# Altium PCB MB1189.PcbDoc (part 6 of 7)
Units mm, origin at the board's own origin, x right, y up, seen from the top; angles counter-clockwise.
Board outline 60.03 x 127.03 mm, 6 copper layers (TOP, L2_GND, L3_VCC, L4_SIG, L5_GND, BOTTOM), stack 1.58 mm thick; 273 components, 264 nets, 1114 pads, 811 vias.
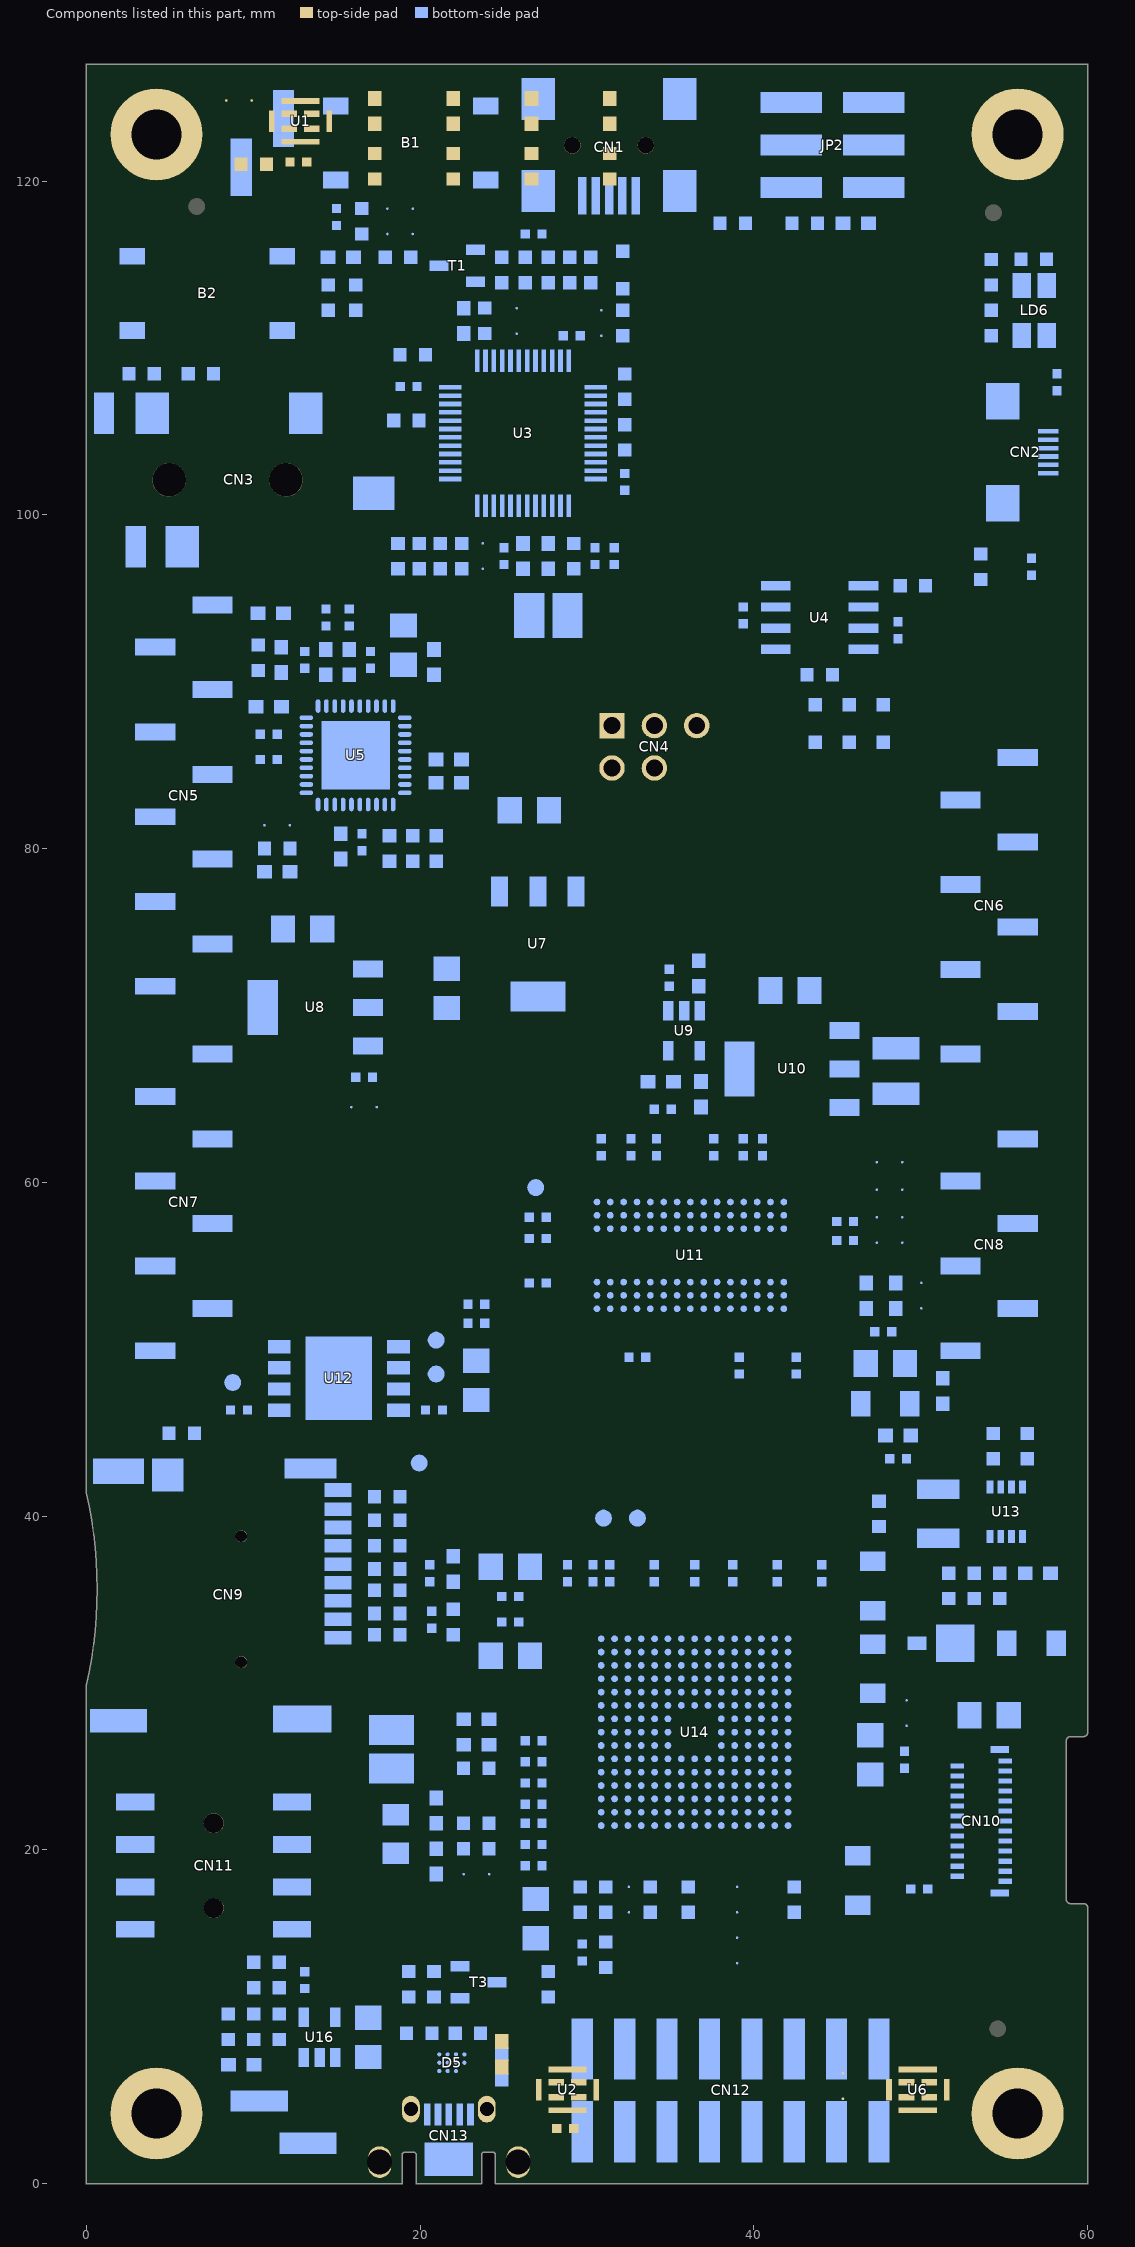
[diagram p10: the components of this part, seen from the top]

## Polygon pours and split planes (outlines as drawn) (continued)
GND on L4_SIG "L4_SIG_GND_P038" (solid, remove dead copper, pour order 38): 21.057,26.848 25.73,26.848 26.492,26.086 26.492,20.498 27.076,19.914 27.076,16.739 26.772,16.434 26.721,16.383 23.495,16.383 16.51,16.383 14.757,18.136 14.757,34.315 13.767,35.306 13.767,39.167 11.989,40.945 9.957,40.945 6.629,44.272 6.629,52.984 5.029,54.585 5.029,58.801 4.42,59.411 4.42,65.634 4.991,66.205 4.991,78.359 9.144,82.512 9.22,82.917 9.22,86.843 8.128,87.935 8.128,92.837 9.22,93.929 13.31,93.929 13.513,93.726 13.513,92.507 13.31,92.304 12.243,92.304 10.058,92.304 9.474,91.719 9.474,91.059 11.481,89.052 11.481,81.915 7.061,77.495 7.061,65.761 5.588,64.287 5.588,60.198 6.909,58.877 6.909,54.839 8.331,53.416 8.331,45.263 10.922,42.672 12.573,42.672 14.859,40.386 14.859,35.941 15.875,34.925 15.875,32.029 21.057,26.848
GND on L4_SIG "L4_SIG_GND_P036" (solid, remove dead copper, pour order 36): 23.724,96.672 31.471,96.672 32.131,96.012 32.131,90.297 31.877,90.043 23.495,90.043 23.114,90.424 23.114,96.063 23.724,96.672
GND on L2_GND (split plane): 211 vertices, not listed, extent 0.5,0.5 59.5,126.5
+3V3 on L3_VCC (split plane): 202 vertices, not listed, extent 0.501,0.501 59.499,126.499
VDD_MCU on L3_VCC (split plane): 25.73,54.291 26.403,53.618 26.414,53.593 26.414,43.815 26.423,43.749 26.432,43.725 26.434,43.717 26.438,43.71 26.448,43.687 26.489,43.634 26.997,43.126 27.05,43.085 27.073,43.075 27.08,43.071 27.088,43.069 27.112,43.06 27.178,43.051 46.353,43.051 46.353,39.603 44.523,37.773 44.482,37.72 44.472,37.697 44.468,37.69 44.466,37.682 44.457,37.658 44.448,37.592 44.448,22.204 42.947,20.703 30.988,20.703 30.922,20.694 30.898,20.685 30.89,20.683 30.883,20.679 30.878,20.676 30.86,20.669 30.807,20.628 27.961,17.782 18.796,17.782 18.73,17.773 18.706,17.764 18.698,17.762 18.691,17.758 18.668,17.748 18.615,17.707 14.043,13.135 14.002,13.082 13.992,13.059 13.988,13.052 13.986,13.044 13.977,13.02 13.968,12.954 13.968,8.763 13.968,4.932 13.483,4.447 9.631,4.447 9.273,4.805 9.273,16.785 12.881,20.393 12.922,20.446 12.929,20.464 12.932,20.469 12.936,20.476 12.938,20.484 12.947,20.508 12.956,20.574 12.956,28.85 14.457,30.351 17.653,30.351 17.719,30.36 17.743,30.369 17.751,30.371 17.758,30.375 17.781,30.385 17.834,30.426 18.85,31.442 18.891,31.495 18.901,31.518 18.905,31.525 18.907,31.533 18.909,31.539 18.916,31.557 18.925,31.623 18.925,53.72 18.936,53.745 19.482,54.291 19.531,54.311 25.681,54.311
+5V on L3_VCC (split plane): 223 vertices, not listed, extent 14.48,9.019 55.751,119.632
+3V3_ST_LINK on L3_VCC (split plane): 30.351,116.713 30.36,116.647 30.369,116.623 30.371,116.615 30.375,116.608 30.385,116.585 30.426,116.532 31.315,115.643 31.368,115.602 31.391,115.592 31.398,115.588 31.406,115.586 31.43,115.577 31.496,115.568 33.493,115.568 33.489,115.536 33.489,97.536 33.495,97.484 25.6,89.589 25.559,89.536 25.549,89.513 25.545,89.506 25.543,89.498 25.534,89.474 25.525,89.408 25.525,82.169 25.534,82.103 25.543,82.079 25.545,82.071 25.549,82.064 25.559,82.041 25.6,81.988 26.489,81.099 26.542,81.058 26.565,81.048 26.572,81.044 26.58,81.042 26.604,81.033 26.67,81.024 32.004,81.024 32.07,81.033 32.094,81.042 32.102,81.044 32.109,81.048 32.132,81.058 32.185,81.099 32.693,81.607 32.734,81.66 32.744,81.683 32.748,81.69 32.75,81.698 32.759,81.722 32.768,81.788 32.768,85.492 33.253,85.977 38.756,85.977 41.273,83.46 41.273,62.359 22.204,62.359 18.925,65.638 18.925,101.854 18.916,101.92 18.907,101.944 18.905,101.952 18.901,101.959 18.891,101.982 18.85,102.035 16.893,103.992 16.893,110.511 26.014,119.632 30.351,119.632
GND on L5_GND (split plane): 208 vertices, not listed, extent 0.5,0.5 59.5,126.5

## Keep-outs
TOP:
  region: 13.073,60.157 13.073,58.417 13.2,58.29 25.525,58.29 25.655,58.42 25.655,60.155 25.528,60.282 13.198,60.282
  region: 13.073,60.407 13.073,62.23 23.75,62.23 23.875,62.105 23.875,60.53 23.627,60.282 13.198,60.282
  region: 8.263,118.491 8.231,118.815 8.137,119.126 7.983,119.413 7.777,119.664 7.526,119.87 7.239,120.024 6.928,120.118 6.604,120.15 6.28,120.118 5.969,120.024 5.778,119.922 5.682,119.87 5.431,119.664 5.225,119.413 5.071,119.126 4.977,118.815 4.945,118.491 4.977,118.167 5.071,117.856 5.225,117.569 5.431,117.318 5.682,117.112 5.778,117.06 5.969,116.958 6.28,116.864 6.604,116.832 6.928,116.864 7.239,116.958 7.526,117.112 7.777,117.318 7.983,117.569 8.137,117.856 8.231,118.167 8.263,118.491
  region: 56.269,9.271 56.237,9.595 56.143,9.906 55.989,10.193 55.783,10.444 55.532,10.65 55.245,10.804 54.934,10.898 54.61,10.93 54.286,10.898 53.975,10.804 53.784,10.702 53.688,10.65 53.437,10.444 53.231,10.193 53.077,9.906 52.983,9.595 52.951,9.271 52.983,8.947 53.077,8.636 53.231,8.349 53.437,8.098 53.688,7.892 53.784,7.84 53.975,7.738 54.286,7.644 54.61,7.612 54.934,7.644 55.245,7.738 55.532,7.892 55.783,8.098 55.989,8.349 56.143,8.636 56.237,8.947 56.269,9.271
  region: 56.015,118.11 55.983,118.434 55.889,118.745 55.735,119.032 55.529,119.283 55.278,119.489 54.991,119.643 54.68,119.737 54.356,119.769 54.032,119.737 53.721,119.643 53.53,119.541 53.434,119.489 53.183,119.283 52.977,119.032 52.823,118.745 52.729,118.434 52.697,118.11 52.729,117.786 52.823,117.475 52.977,117.188 53.183,116.937 53.434,116.731 53.53,116.679 53.721,116.577 54.032,116.483 54.356,116.451 54.68,116.483 54.991,116.577 55.278,116.731 55.529,116.937 55.735,117.188 55.889,117.475 55.983,117.786 56.015,118.11
BOTTOM:
  region: 8.135,118.491 8.106,118.79 8.019,119.077 7.877,119.342 7.687,119.574 7.455,119.764 7.19,119.906 6.903,119.993 6.604,120.022 6.305,119.993 6.018,119.906 5.842,119.812 5.753,119.764 5.521,119.574 5.331,119.342 5.189,119.077 5.102,118.79 5.073,118.491 5.102,118.192 5.189,117.905 5.331,117.64 5.521,117.408 5.753,117.218 5.842,117.17 6.018,117.076 6.305,116.989 6.604,116.96 6.903,116.989 7.19,117.076 7.455,117.218 7.687,117.408 7.877,117.64 8.019,117.905 8.106,118.192 8.135,118.491
  region: 8.263,118.491 8.231,118.815 8.137,119.126 7.983,119.413 7.777,119.664 7.526,119.87 7.239,120.024 6.928,120.118 6.604,120.15 6.28,120.118 5.969,120.024 5.778,119.922 5.682,119.87 5.431,119.664 5.225,119.413 5.071,119.126 4.977,118.815 4.945,118.491 4.977,118.167 5.071,117.856 5.225,117.569 5.431,117.318 5.682,117.112 5.778,117.06 5.969,116.958 6.28,116.864 6.604,116.832 6.928,116.864 7.239,116.958 7.526,117.112 7.777,117.318 7.983,117.569 8.137,117.856 8.231,118.167 8.263,118.491
  region: 56.015,118.11 55.983,118.434 55.889,118.745 55.735,119.032 55.529,119.283 55.278,119.489 54.991,119.643 54.68,119.737 54.356,119.769 54.032,119.737 53.721,119.643 53.53,119.541 53.434,119.489 53.183,119.283 52.977,119.032 52.823,118.745 52.729,118.434 52.697,118.11 52.729,117.786 52.823,117.475 52.977,117.188 53.183,116.937 53.434,116.731 53.53,116.679 53.721,116.577 54.032,116.483 54.356,116.451 54.68,116.483 54.991,116.577 55.278,116.731 55.529,116.937 55.735,117.188 55.889,117.475 55.983,117.786 56.015,118.11
  region: 55.887,118.11 55.858,118.409 55.771,118.696 55.629,118.961 55.439,119.193 55.207,119.383 54.942,119.525 54.655,119.612 54.356,119.641 54.057,119.612 53.77,119.525 53.594,119.431 53.505,119.383 53.273,119.193 53.083,118.961 52.941,118.696 52.854,118.409 52.825,118.11 52.854,117.811 52.941,117.524 53.083,117.259 53.273,117.027 53.505,116.837 53.594,116.789 53.77,116.695 54.057,116.608 54.356,116.579 54.655,116.608 54.942,116.695 55.207,116.837 55.439,117.027 55.629,117.259 55.771,117.524 55.858,117.811 55.887,118.11
  region: 56.269,9.271 56.237,9.595 56.143,9.906 55.989,10.193 55.783,10.444 55.532,10.65 55.245,10.804 54.934,10.898 54.61,10.93 54.286,10.898 53.975,10.804 53.784,10.702 53.688,10.65 53.437,10.444 53.231,10.193 53.077,9.906 52.983,9.595 52.951,9.271 52.983,8.947 53.077,8.636 53.231,8.349 53.437,8.098 53.688,7.892 53.784,7.84 53.975,7.738 54.286,7.644 54.61,7.612 54.934,7.644 55.245,7.738 55.532,7.892 55.783,8.098 55.989,8.349 56.143,8.636 56.237,8.947 56.269,9.271
  region: 56.141,9.271 56.112,9.57 56.025,9.857 55.883,10.122 55.693,10.354 55.461,10.544 55.196,10.686 54.909,10.773 54.61,10.802 54.311,10.773 54.024,10.686 53.848,10.592 53.759,10.544 53.527,10.354 53.337,10.122 53.195,9.857 53.108,9.57 53.079,9.271 53.108,8.972 53.195,8.685 53.337,8.42 53.527,8.188 53.759,7.998 53.848,7.95 54.024,7.856 54.311,7.769 54.61,7.74 54.909,7.769 55.196,7.856 55.461,7.998 55.693,8.188 55.883,8.42 56.025,8.685 56.112,8.972 56.141,9.271
  region: 56.015,118.11 55.983,118.434 55.889,118.745 55.735,119.032 55.529,119.283 55.278,119.489 54.991,119.643 54.68,119.737 54.356,119.769 54.032,119.737 53.721,119.643 53.53,119.541 53.434,119.489 53.183,119.283 52.977,119.032 52.823,118.745 52.729,118.434 52.697,118.11 52.729,117.786 52.823,117.475 52.977,117.188 53.183,116.937 53.434,116.731 53.53,116.679 53.721,116.577 54.032,116.483 54.356,116.451 54.68,116.483 54.991,116.577 55.278,116.731 55.529,116.937 55.735,117.188 55.889,117.475 55.983,117.786 56.015,118.11
  region: 8.263,118.491 8.231,118.815 8.137,119.126 7.983,119.413 7.777,119.664 7.526,119.87 7.239,120.024 6.928,120.118 6.604,120.15 6.28,120.118 5.969,120.024 5.778,119.922 5.682,119.87 5.431,119.664 5.225,119.413 5.071,119.126 4.977,118.815 4.945,118.491 4.977,118.167 5.071,117.856 5.225,117.569 5.431,117.318 5.682,117.112 5.778,117.06 5.969,116.958 6.28,116.864 6.604,116.832 6.928,116.864 7.239,116.958 7.526,117.112 7.777,117.318 7.983,117.569 8.137,117.856 8.231,118.167 8.263,118.491
  region: 8.135,118.491 8.106,118.79 8.019,119.077 7.877,119.342 7.687,119.574 7.455,119.764 7.19,119.906 6.903,119.993 6.604,120.022 6.305,119.993 6.018,119.906 5.842,119.812 5.753,119.764 5.521,119.574 5.331,119.342 5.189,119.077 5.102,118.79 5.073,118.491 5.102,118.192 5.189,117.905 5.331,117.64 5.521,117.408 5.753,117.218 5.842,117.17 6.018,117.076 6.305,116.989 6.604,116.96 6.903,116.989 7.19,117.076 7.455,117.218 7.687,117.408 7.877,117.64 8.019,117.905 8.106,118.192 8.135,118.491
  region: 55.887,118.11 55.858,118.409 55.771,118.696 55.629,118.961 55.439,119.193 55.207,119.383 54.942,119.525 54.655,119.612 54.356,119.641 54.057,119.612 53.77,119.525 53.594,119.431 53.505,119.383 53.273,119.193 53.083,118.961 52.941,118.696 52.854,118.409 52.825,118.11 52.854,117.811 52.941,117.524 53.083,117.259 53.273,117.027 53.505,116.837 53.594,116.789 53.77,116.695 54.057,116.608 54.356,116.579 54.655,116.608 54.942,116.695 55.207,116.837 55.439,117.027 55.629,117.259 55.771,117.524 55.858,117.811 55.887,118.11
  region: 56.269,9.271 56.237,9.595 56.143,9.906 55.989,10.193 55.783,10.444 55.532,10.65 55.245,10.804 54.934,10.898 54.61,10.93 54.286,10.898 53.975,10.804 53.784,10.702 53.688,10.65 53.437,10.444 53.231,10.193 53.077,9.906 52.983,9.595 52.951,9.271 52.983,8.947 53.077,8.636 53.231,8.349 53.437,8.098 53.688,7.892 53.784,7.84 53.975,7.738 54.286,7.644 54.61,7.612 54.934,7.644 55.245,7.738 55.532,7.892 55.783,8.098 55.989,8.349 56.143,8.636 56.237,8.947 56.269,9.271
  region: 56.141,9.271 56.112,9.57 56.025,9.857 55.883,10.122 55.693,10.354 55.461,10.544 55.196,10.686 54.909,10.773 54.61,10.802 54.311,10.773 54.024,10.686 53.848,10.592 53.759,10.544 53.527,10.354 53.337,10.122 53.195,9.857 53.108,9.57 53.079,9.271 53.108,8.972 53.195,8.685 53.337,8.42 53.527,8.188 53.759,7.998 53.848,7.95 54.024,7.856 54.311,7.769 54.61,7.74 54.909,7.769 55.196,7.856 55.461,7.998 55.693,8.188 55.883,8.42 56.025,8.685 56.112,8.972 56.141,9.271
Multi-Layer:
  region: 33.492,97.028 52.508,97.028 52.508,116.044 33.492,116.044

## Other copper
TOP:
  pour cut-out: 17.231,96.774 17.195,96.953 17.094,97.104 16.943,97.205 16.764,97.241 16.585,97.205 16.535,97.171 16.434,97.104 16.333,96.953 16.297,96.774 16.333,96.595 16.434,96.444 16.535,96.377 16.585,96.343 16.764,96.307 16.943,96.343 17.094,96.444 17.195,96.595 17.231,96.774
  pour cut-out: 18.196,90.932 18.16,91.111 18.059,91.262 17.908,91.363 17.729,91.399 17.551,91.363 17.5,91.329 17.399,91.262 17.298,91.111 17.263,90.932 17.298,90.753 17.399,90.602 17.5,90.535 17.551,90.501 17.729,90.465 17.908,90.501 18.059,90.602 18.16,90.753 18.196,90.932
  pour cut-out: 17.846,81.808 17.81,81.987 17.709,82.138 17.558,82.239 17.379,82.275 17.2,82.239 17.15,82.205 17.049,82.138 16.948,81.987 16.912,81.808 16.948,81.629 17.049,81.478 17.15,81.411 17.2,81.377 17.379,81.341 17.558,81.377 17.709,81.478 17.81,81.629 17.846,81.808
  pour cut-out: 13.294,89.916 13.258,90.095 13.157,90.246 13.006,90.347 12.827,90.383 12.648,90.347 12.598,90.313 12.497,90.246 12.396,90.095 12.36,89.916 12.396,89.737 12.497,89.586 12.598,89.519 12.648,89.485 12.827,89.449 13.006,89.485 13.157,89.586 13.258,89.737 13.294,89.916
  pour cut-out: 12.129,93.472 12.15,93.443 12.168,93.413 12.184,93.381 12.197,93.348 12.206,93.314 12.213,93.279 12.217,93.244 12.218,93.208 12.215,93.173 12.21,93.138 12.201,93.103 12.19,93.07 12.176,93.037 12.158,93.006 12.139,92.977 12.116,92.949 12.092,92.923 12.065,92.9 12.036,92.879 12.006,92.861 11.974,92.845 11.941,92.832 11.907,92.823 11.872,92.816 11.837,92.812 11.801,92.811 11.766,92.814 11.731,92.819 11.696,92.828 11.663,92.839 11.63,92.853 11.599,92.871 11.57,92.89 11.542,92.913 11.516,92.937 11.493,92.964 11.472,92.993 11.454,93.023 11.438,93.055 11.425,93.088 11.416,93.122 11.409,93.157 11.405,93.192 11.404,93.228 11.407,93.263 11.412,93.298 11.421,93.333 11.432,93.366 11.446,93.399 11.464,93.43 11.483,93.459 11.493,93.472 11.493,93.959 17.335,99.801 17.335,102.544 19.748,104.957 19.748,107.447 20.256,107.955 20.256,111.815 20.88,112.44 20.883,112.456 20.89,112.491 20.9,112.525 20.912,112.558 20.928,112.59 20.946,112.62 20.967,112.649 20.991,112.676 21.016,112.7 21.044,112.723 21.074,112.743 21.105,112.76 21.137,112.774 21.171,112.785 21.205,112.794 21.24,112.799 21.276,112.802 21.311,112.801 21.346,112.797 21.381,112.79 21.415,112.781 21.448,112.768 21.48,112.752 21.511,112.734 21.539,112.713 21.566,112.689 21.591,112.664 21.613,112.636 21.633,112.607 21.65,112.576 21.664,112.543 21.676,112.51 21.684,112.475 21.69,112.44 21.692,112.405 21.691,112.369 21.687,112.334 21.681,112.299 21.671,112.265 21.658,112.232 21.642,112.2 21.624,112.17 21.603,112.141 21.58,112.114 21.554,112.09 21.526,112.067 21.497,112.047 21.466,112.03 21.433,112.016 21.4,112.005 21.365,111.996 21.346,111.993 21.33,111.99 20.892,111.552 20.892,107.691 20.384,107.183 20.384,104.694 17.971,102.281 17.971,99.538 12.129,93.696 12.129,93.472
  pour cut-out: 24.385,23.533 24.385,17.615 24.411,17.592 24.436,17.566 24.458,17.538 24.478,17.509 24.495,17.478 24.509,17.445 24.521,17.411 24.529,17.377 24.534,17.342 24.537,17.307 24.536,17.271 24.532,17.236 24.525,17.201 24.515,17.167 24.503,17.134 24.487,17.102 24.468,17.072 24.447,17.043 24.424,17.016 24.398,16.992 24.371,16.969 24.341,16.95 24.31,16.933 24.278,16.918 24.244,16.907 24.21,16.898 24.175,16.893 24.139,16.891 24.104,16.891 24.068,16.895 24.034,16.902 23.999,16.912 23.966,16.925 23.934,16.941 23.904,16.959 23.875,16.98 23.849,17.003 23.824,17.029 23.802,17.057 23.782,17.086 23.765,17.117 23.751,17.15 23.739,17.183 23.731,17.218 23.726,17.253 23.723,17.288 23.724,17.324 23.728,17.359 23.735,17.394 23.745,17.428 23.757,17.461 23.773,17.493 23.792,17.523 23.813,17.552 23.836,17.579 23.862,17.603 23.875,17.615 23.875,23.533 23.849,23.556 23.824,23.582 23.802,23.61 23.782,23.639 23.765,23.67 23.751,23.703 23.739,23.737 23.731,23.771 23.726,23.806 23.723,23.841 23.724,23.877 23.728,23.912 23.735,23.947 23.745,23.981 23.757,24.014 23.773,24.046 23.792,24.076 23.813,24.105 23.836,24.132 23.862,24.156 23.889,24.179 23.919,24.198 23.95,24.215 23.982,24.23 24.016,24.241 24.05,24.25 24.085,24.255 24.121,24.257 24.156,24.257 24.192,24.253 24.226,24.246 24.261,24.236 24.294,24.223 24.326,24.207 24.356,24.189 24.385,24.168 24.411,24.145 24.436,24.119 24.458,24.091 24.478,24.062 24.495,24.031 24.509,23.998 24.521,23.965 24.529,23.93 24.534,23.895 24.537,23.86 24.536,23.824 24.532,23.789 24.525,23.754 24.515,23.72 24.503,23.687 24.487,23.655 24.468,23.625 24.447,23.596 24.424,23.569 24.398,23.545 24.385,23.533
  pour cut-out: 23.021,17.272 22.989,17.431 22.899,17.565 22.765,17.655 22.606,17.687 22.447,17.655 22.402,17.625 22.313,17.565 22.223,17.431 22.191,17.272 22.223,17.113 22.313,16.979 22.402,16.919 22.447,16.889 22.606,16.857 22.765,16.889 22.899,16.979 22.989,17.113 23.021,17.272
  text "1" at 13.805,60.82 h1.4
  text "B" at 13.729,58.801 h1.4
  text "TOP" at 55.499,-49.276 h1.52
  text "1" at 62.24,-49.31 h1.91
  text ".GTL" at 97.47,-49.4 h1.52
L4_SIG:
  pour cut-out: 24.545,23.851 24.513,24.009 24.423,24.144 24.289,24.234 24.13,24.265 23.971,24.234 23.926,24.204 23.837,24.144 23.747,24.009 23.715,23.851 23.747,23.692 23.837,23.557 23.926,23.497 23.971,23.467 24.13,23.436 24.289,23.467 24.423,23.557 24.513,23.692 24.545,23.851
  pour cut-out: 18.628,78.232 18.592,78.411 18.491,78.562 18.34,78.663 18.161,78.699 17.982,78.663 17.932,78.629 17.831,78.562 17.73,78.411 17.694,78.232 17.73,78.053 17.831,77.902 17.932,77.835 17.982,77.801 18.161,77.765 18.34,77.801 18.491,77.902 18.592,78.053 18.628,78.232
  pour cut-out: 20.025,78.232 19.989,78.411 19.888,78.562 19.737,78.663 19.558,78.699 19.379,78.663 19.329,78.629 19.228,78.562 19.127,78.411 19.091,78.232 19.127,78.053 19.228,77.902 19.329,77.835 19.379,77.801 19.558,77.765 19.737,77.801 19.888,77.902 19.989,78.053 20.025,78.232
  pour cut-out: 17.436,89.388 17.4,89.567 17.299,89.718 17.148,89.819 16.969,89.855 16.79,89.819 16.74,89.785 16.639,89.718 16.538,89.567 16.502,89.388 16.538,89.21 16.639,89.058 16.74,88.991 16.79,88.957 16.969,88.922 17.148,88.957 17.299,89.058 17.4,89.21 17.436,89.388
  pour cut-out: 16.977,78.842 16.941,79.02 16.84,79.172 16.689,79.273 16.51,79.308 16.331,79.273 16.281,79.239 16.18,79.172 16.079,79.02 16.043,78.842 16.079,78.663 16.18,78.512 16.281,78.444 16.331,78.41 16.51,78.375 16.689,78.41 16.84,78.512 16.941,78.663 16.977,78.842
  pour cut-out: 14.945,78.613 14.909,78.792 14.808,78.943 14.657,79.044 14.478,79.08 14.299,79.044 14.249,79.01 14.148,78.943 14.047,78.792 14.011,78.613 14.047,78.434 14.148,78.283 14.249,78.216 14.299,78.182 14.478,78.146 14.657,78.182 14.808,78.283 14.909,78.434 14.945,78.613
  pour cut-out: 13.548,79.121 13.512,79.3 13.411,79.451 13.26,79.552 13.081,79.588 12.902,79.552 12.852,79.518 12.751,79.451 12.65,79.3 12.614,79.121 12.65,78.942 12.751,78.791 12.852,78.724 12.902,78.69 13.081,78.654 13.26,78.69 13.411,78.791 13.512,78.942 13.548,79.121
  text "4" at 19.71,60.833 h1.4
  text "B" at 19.71,58.801 h1.4
  text "L4 SIGNAL" at 55.77,-49.21 h1.52
  text ".G1" at 97.43,-49.36 h1.52
  text "4" at 67.96,-49.41 h1.91
BOTTOM:
  pour cut-out: 34.394,67.164 34.394,68.613 35.334,68.613 35.334,67.164 34.394,67.164
  pour cut-out: 40.235,123.926 40.235,125.502 44.223,125.502 44.223,123.926 40.235,123.926
  pour cut-out: 40.235,121.386 40.235,122.962 44.223,122.962 44.223,121.386 40.235,121.386
  pour cut-out: 40.235,118.846 40.235,120.422 44.223,120.422 44.223,118.846 40.235,118.846
  pour cut-out: 24.358,81.381 24.358,83.211 25.934,83.211 25.934,81.381 24.358,81.381
  pour cut-out: 51.028,67.03 51.028,68.352 53.747,68.352 53.747,67.03 51.028,67.03
  pour cut-out: 46.964,64.058 46.964,65.863 50.064,65.863 50.064,64.058 46.964,64.058
  pour cut-out: 44.386,63.841 44.386,65.163 46.496,65.163 46.496,63.841 44.386,63.841
  pour cut-out: 15.811,69.824 15.811,71.146 17.921,71.146 17.921,69.824 15.811,69.824
  pour cut-out: 10.769,74.269 10.769,76.099 12.345,76.099 12.345,74.269 10.769,74.269
  pour cut-out: 9.511,68.681 9.511,72.289 11.62,72.289 11.62,68.681 9.511,68.681
  pour cut-out: 46.964,67.487 46.964,69.292 50.064,69.292 50.064,67.487 46.964,67.487
  pour cut-out: 44.386,68.441 44.386,69.763 46.496,69.763 46.496,68.441 44.386,68.441
  pour cut-out: 42.773,70.586 42.773,72.416 44.349,72.416 44.349,70.586 42.773,70.586
  pour cut-out: 54.457,74.65 54.457,75.972 57.176,75.972 57.176,74.65 54.457,74.65
  pour cut-out: 26.39,76.391 26.39,78.5 27.712,78.5 27.712,76.391 26.39,76.391
  pour cut-out: 25.247,70.09 25.247,72.2 28.855,72.2 28.855,70.09 25.247,70.09
  pour cut-out: 15.976,6.578 15.976,8.154 17.806,8.154 17.806,6.578 15.976,6.578
  pour cut-out: 50.749,46.139 50.749,47.333 51.867,47.333 51.867,46.139 50.749,46.139
  pour cut-out: 49.631,40.868 49.631,42.342 52.477,42.342 52.477,40.868 49.631,40.868
  pour cut-out: 38.086,64.998 38.086,68.606 40.195,68.606 40.195,64.998 38.086,64.998
  pour cut-out: 46.177,51.854 46.177,53.048 47.295,53.048 47.295,51.854 46.177,51.854
  pour cut-out: 45.694,48.234 45.694,50.064 47.27,50.064 47.27,48.234 45.694,48.234
  pour cut-out: 45.669,45.821 45.669,47.651 47.143,47.651 47.143,45.821 45.669,45.821
  pour cut-out: 40.276,91.516 40.276,92.38 42.36,92.38 42.36,91.516 40.276,91.516
  pour cut-out: 40.276,92.786 40.276,93.65 42.36,93.65 42.36,92.786 40.276,92.786
  text "6" at 23.203,60.833 h1.4
  text "B" at 23.216,58.801 h1.4
  text ".GBL" at 97.94,-49.12 h1.52
  text "6" at 65.5,-49.21 h1.91
  text "BOTTOM" at 55.499,-49.276 h1.52
L2_GND (plane layer: these items are gaps in the copper):
  region: 16.637,62.23 25.401,62.23 25.655,61.976 25.655,60.452 25.506,60.303 25.655,60.155 25.655,58.42 25.527,58.292 14.986,58.292 14.986,58.42 16.637,58.42 16.637,60.071 14.986,60.071 14.986,60.452 16.637,60.452 16.637,62.103 14.986,62.103 14.986,62.23
  region: 14.986,62.23 11.261,62.23 11.134,62.103 11.134,60.528 11.405,60.258 11.175,60.028 11.175,58.547 11.43,58.292 14.986,58.292
  pour cut-out: 52.508,116.044 52.508,97.027 33.491,97.027 33.491,116.044 52.508,116.044
  pour cut-out: 34.427,122.151 34.396,122.386 34.305,122.605 34.16,122.793 33.972,122.938 33.753,123.028 33.518,123.059 33.283,123.028 33.064,122.938 32.876,122.793 32.731,122.605 32.641,122.386 32.61,122.151 32.641,121.916 32.731,121.697 32.876,121.509 33.064,121.364 33.283,121.273 33.518,121.242 33.753,121.273 33.972,121.364 34.16,121.509 34.305,121.697 34.396,121.916 34.427,122.151
  pour cut-out: 30.027,122.151 29.996,122.386 29.905,122.605 29.76,122.793 29.572,122.938 29.353,123.028 29.118,123.059 28.883,123.028 28.664,122.938 28.476,122.793 28.331,122.605 28.241,122.386 28.21,122.151 28.241,121.916 28.331,121.697 28.476,121.509 28.664,121.364 28.883,121.273 29.118,121.242 29.353,121.273 29.572,121.364 29.76,121.509 29.905,121.697 29.996,121.916 30.027,122.151
  pour cut-out: 8.629,16.51 8.595,16.771 8.494,17.015 8.334,17.224 8.125,17.384 7.881,17.485 7.62,17.519 7.359,17.485 7.115,17.384 6.906,17.224 6.746,17.015 6.645,16.771 6.611,16.51 6.645,16.249 6.746,16.005 6.906,15.796 7.115,15.636 7.359,15.535 7.62,15.501 7.881,15.535 8.125,15.636 8.334,15.796 8.494,16.005 8.595,16.249 8.629,16.51
  pour cut-out: 8.629,21.59 8.595,21.851 8.494,22.095 8.334,22.304 8.125,22.464 7.881,22.565 7.62,22.599 7.359,22.565 7.115,22.464 6.906,22.304 6.746,22.095 6.645,21.851 6.611,21.59 6.645,21.329 6.746,21.085 6.906,20.876 7.115,20.716 7.359,20.615 7.62,20.581 7.881,20.615 8.125,20.716 8.334,20.876 8.494,21.085 8.595,21.329 8.629,21.59
  pour cut-out: 6.346,102.108 6.298,102.468 6.159,102.804 5.938,103.093 5.649,103.314 5.313,103.453 4.953,103.501 4.593,103.453 4.257,103.314 3.968,103.093 3.747,102.804 3.608,102.468 3.56,102.108 3.608,101.748 3.747,101.412 3.968,101.123 4.257,100.902 4.593,100.763 4.953,100.715 5.313,100.763 5.649,100.902 5.938,101.123 6.159,101.412 6.298,101.748 6.346,102.108
  pour cut-out: 10.015,31.242 9.989,31.434 9.915,31.614 9.797,31.768 9.643,31.886 9.463,31.96 9.271,31.986 9.079,31.96 8.899,31.886 8.745,31.768 8.627,31.614 8.553,31.434 8.527,31.242 8.553,31.05 8.627,30.87 8.745,30.716 8.899,30.598 9.079,30.524 9.271,30.498 9.463,30.524 9.643,30.598 9.797,30.716 9.915,30.87 9.989,31.05 10.015,31.242
  pour cut-out: 10.015,38.792 9.989,38.984 9.915,39.164 9.797,39.318 9.643,39.436 9.463,39.51 9.271,39.536 9.079,39.51 8.899,39.436 8.745,39.318 8.627,39.164 8.553,38.984 8.527,38.792 8.553,38.599 8.627,38.42 8.745,38.266 8.899,38.148 9.079,38.074 9.271,38.048 9.463,38.074 9.643,38.148 9.797,38.266 9.915,38.42 9.989,38.599 10.015,38.792
  pour cut-out: 13.346,102.108 13.298,102.468 13.159,102.804 12.938,103.093 12.649,103.314 12.313,103.453 11.953,103.501 11.593,103.453 11.257,103.314 10.968,103.093 10.747,102.804 10.608,102.468 10.56,102.108 10.608,101.748 10.747,101.412 10.968,101.123 11.257,100.902 11.593,100.763 11.953,100.715 12.313,100.763 12.649,100.902 12.938,101.123 13.159,101.412 13.298,101.748 13.346,102.108
  lines w0.254: 0.371,126.492 0.392,126.544 0.411,126.589 ; 0.371,126.492 0.371,126.492 ; 0.371,126.492 0.371,126.492 ; 0.371,126.492 0.396,41.453 0.402,41.438 0.399,41.423 0.728,39.931 0.955,37.986 1.031,36.824 1.056,35.409 1.006,34.043 0.905,32.654 0.703,31.215 0.374,29.67 0.376,29.656 0.371,29.642 0.371,0.508 0.411,0.411 0.508,0.371 18.669,0.371 18.766,0.411 ; 0.411,126.589 0.462,126.61 0.508,126.629 ; 0.411,126.589 0.411,126.589 ; 0.411,126.589 0.411,126.589 ; 0.508,126.629 59.492,126.629 59.589,126.589 59.629,126.492 59.629,27.305 59.589,27.208 59.492,27.167 58.97,27.167 58.913,27.165 58.859,27.158 58.806,27.146 58.754,27.129 58.703,27.109 58.655,27.083 58.609,27.054 58.566,27.021 58.526,26.984 58.489,26.944 58.456,26.901 58.426,26.855 58.401,26.807 58.38,26.756 58.364,26.704 58.352,26.651 58.345,26.597 58.343,26.54 58.343,17.021 58.345,16.963 58.352,16.909 58.364,16.856 58.38,16.804 58.401,16.754 58.426,16.706 58.456,16.66 58.489,16.616 58.526,16.576 58.566,16.539 58.609,16.506 58.655,16.477 58.703,16.452 58.754,16.431 58.806,16.415 58.859,16.403 58.913,16.396 58.97,16.393 59.492,16.393 59.589,16.353 59.629,16.256 59.629,0.508 59.589,0.411 59.492,0.371 24.74,0.371 ; 0.508,126.629 0.508,126.629 ; 0.508,126.629 0.508,126.629 ; 18.766,0.411 18.766,0.411 ; 18.766,0.411 18.842,0.487 18.883,0.584 ; 18.883,0.584 18.883,0.584 ; 18.883,0.584 18.883,1.975 18.904,1.996 19.806,1.996 19.827,1.975 19.827,0.66 ; 19.827,0.66 19.827,0.66 ; 19.827,0.66 19.855,0.592 19.867,0.563 ; 19.867,0.563 19.867,0.563 ; 19.867,0.563 20.02,0.411 20.117,0.371 ; 20.117,0.371 20.117,0.371 ; 20.117,0.371 23.393,0.371 23.491,0.411 ; 23.491,0.411 23.491,0.411 ; 23.491,0.411 23.541,0.462 23.582,0.559 ; 23.582,0.559 23.582,0.559 ; 23.582,0.559 23.582,1.95 23.603,1.971 24.454,1.971 24.526,1.899 24.526,0.584 24.566,0.487 ; 24.566,0.487 24.566,0.487 ; 24.566,0.487 24.642,0.411 24.74,0.371 ; 24.74,0.371 24.74,0.371
  text "2" at 15.507,60.846 h1.4
  text "B" at 15.469,58.852 h1.4
  text "2" at 65.15,-49.31 h1.91
  text "L2 GND" at 55.77,-49.41 h1.52
  text ".GP1" at 97.59,-49.47 h1.52
L3_VCC (plane layer: these items are gaps in the copper):
  region: 16.777,62.23 25.401,62.23 25.655,61.976 25.655,60.452 25.506,60.303 25.655,60.155 25.655,58.42 25.527,58.292 16.777,58.292 16.777,58.42 18.377,58.42 18.377,60.071 16.777,60.071 16.777,60.452 18.377,60.452 18.377,62.103 16.777,62.103
  region: 16.777,62.23 11.261,62.23 11.134,62.103 11.134,60.528 11.405,60.258 11.175,60.028 11.175,58.547 11.43,58.292 16.777,58.292
  pour cut-out: 10.015,38.792 9.989,38.984 9.915,39.164 9.797,39.318 9.643,39.436 9.463,39.51 9.271,39.536 9.079,39.51 8.899,39.436 8.745,39.318 8.627,39.164 8.553,38.984 8.527,38.792 8.553,38.599 8.627,38.42 8.745,38.266 8.899,38.148 9.079,38.074 9.271,38.048 9.463,38.074 9.643,38.148 9.797,38.266 9.915,38.42 9.989,38.599 10.015,38.792
  pour cut-out: 10.015,31.242 9.989,31.434 9.915,31.614 9.797,31.768 9.643,31.886 9.463,31.96 9.271,31.986 9.079,31.96 8.899,31.886 8.745,31.768 8.627,31.614 8.553,31.434 8.527,31.242 8.553,31.05 8.627,30.87 8.745,30.716 8.899,30.598 9.079,30.524 9.271,30.498 9.463,30.524 9.643,30.598 9.797,30.716 9.915,30.87 9.989,31.05 10.015,31.242
  pour cut-out: 13.346,102.108 13.298,102.468 13.159,102.804 12.938,103.093 12.649,103.314 12.313,103.453 11.953,103.501 11.593,103.453 11.257,103.314 10.968,103.093 10.747,102.804 10.608,102.468 10.56,102.108 10.608,101.748 10.747,101.412 10.968,101.123 11.257,100.902 11.593,100.763 11.953,100.715 12.313,100.763 12.649,100.902 12.938,101.123 13.159,101.412 13.298,101.748 13.346,102.108
  pour cut-out: 6.346,102.108 6.298,102.468 6.159,102.804 5.938,103.093 5.649,103.314 5.313,103.453 4.953,103.501 4.593,103.453 4.257,103.314 3.968,103.093 3.747,102.804 3.608,102.468 3.56,102.108 3.608,101.748 3.747,101.412 3.968,101.123 4.257,100.902 4.593,100.763 4.953,100.715 5.313,100.763 5.649,100.902 5.938,101.123 6.159,101.412 6.298,101.748 6.346,102.108
  pour cut-out: 8.629,21.59 8.595,21.851 8.494,22.095 8.334,22.304 8.125,22.464 7.881,22.565 7.62,22.599 7.359,22.565 7.115,22.464 6.906,22.304 6.746,22.095 6.645,21.851 6.611,21.59 6.645,21.329 6.746,21.085 6.906,20.876 7.115,20.716 7.359,20.615 7.62,20.581 7.881,20.615 8.125,20.716 8.334,20.876 8.494,21.085 8.595,21.329 8.629,21.59
  pour cut-out: 8.629,16.51 8.595,16.771 8.494,17.015 8.334,17.224 8.125,17.384 7.881,17.485 7.62,17.519 7.359,17.485 7.115,17.384 6.906,17.224 6.746,17.015 6.645,16.771 6.611,16.51 6.645,16.249 6.746,16.005 6.906,15.796 7.115,15.636 7.359,15.535 7.62,15.501 7.881,15.535 8.125,15.636 8.334,15.796 8.494,16.005 8.595,16.249 8.629,16.51
  pour cut-out: 30.027,122.151 29.996,122.386 29.905,122.605 29.76,122.793 29.572,122.938 29.353,123.028 29.118,123.059 28.883,123.028 28.664,122.938 28.476,122.793 28.331,122.605 28.241,122.386 28.21,122.151 28.241,121.916 28.331,121.697 28.476,121.509 28.664,121.364 28.883,121.273 29.118,121.242 29.353,121.273 29.572,121.364 29.76,121.509 29.905,121.697 29.996,121.916 30.027,122.151
  pour cut-out: 34.427,122.151 34.396,122.386 34.305,122.605 34.16,122.793 33.972,122.938 33.753,123.028 33.518,123.059 33.283,123.028 33.064,122.938 32.876,122.793 32.731,122.605 32.641,122.386 32.61,122.151 32.641,121.916 32.731,121.697 32.876,121.509 33.064,121.364 33.283,121.273 33.518,121.242 33.753,121.273 33.972,121.364 34.16,121.509 34.305,121.697 34.396,121.916 34.427,122.151
  lines w0.254: 9.134,4.804 9.134,16.786 ; 9.134,4.804 9.134,4.804 ; 9.134,4.804 9.162,4.735 9.174,4.707 ; 9.134,16.786 9.174,16.883 12.817,20.526 12.817,28.851 ; 9.134,16.786 9.134,16.786 ; 9.174,4.707 9.174,4.707 ; 9.174,4.707 9.533,4.348 9.63,4.308 ; 9.63,4.308 9.63,4.308 ; 9.63,4.308 13.484,4.308 13.581,4.348 ; 12.817,28.851 12.857,28.948 14.359,30.45 14.456,30.49 ; 12.817,28.851 12.817,28.851 ; 13.581,4.348 13.581,4.348 ; 13.581,4.348 14.067,4.834 14.107,4.931 ; 14.107,4.931 14.107,4.931 ; 14.107,4.931 14.107,13.002 18.748,17.643 27.962,17.643 ; 14.341,12.849 14.381,12.946 18.804,17.369 ; 14.341,12.849 14.341,12.849 ; 14.341,12.849 14.341,9.017 14.381,8.92 14.478,8.88 16.405,8.88 16.502,8.92 17.224,9.642 26.819,9.642 26.916,9.682 ; 14.456,30.49 17.701,30.49 18.786,31.575 18.786,53.721 ; 14.456,30.49 14.456,30.49 ; 16.754,103.991 16.754,110.512 ; 16.754,103.991 16.754,103.991 ; 16.754,103.991 16.794,103.894 18.786,101.902 18.786,65.637 18.826,65.54 ; 16.754,110.512 16.794,110.609 25.916,119.731 ; 16.754,110.512 16.754,110.512 ; 18.766,0.412 18.669,0.372 0.509,0.372 0.412,0.412 0.372,0.509 0.372,29.667 0.377,29.68 0.374,29.694 0.905,32.378 1.056,34.499 1.082,35.912 0.93,38.062 0.728,39.906 0.375,41.499 0.378,41.515 0.372,41.529 0.372,126.491 0.412,126.588 0.509,126.628 59.491,126.628 59.588,126.588 59.628,126.491 59.628,27.306 59.588,27.209 59.491,27.168 58.97,27.168 58.913,27.166 58.859,27.159 58.805,27.147 58.753,27.13 58.703,27.11 58.654,27.084 58.608,27.055 58.565,27.022 58.525,26.985 58.488,26.945 58.455,26.901 58.425,26.855 58.4,26.807 58.379,26.757 58.363,26.705 58.351,26.651 58.344,26.597 58.342,26.54 58.342,17.021 58.344,16.963 58.351,16.909 58.363,16.856 58.379,16.804 58.4,16.753 58.425,16.705 58.455,16.659 58.488,16.616 58.525,16.576 58.565,16.539 58.608,16.505 58.654,16.476 58.703,16.451 58.753,16.43 58.805,16.414 58.859,16.402 58.913,16.395 58.97,16.392 59.491,16.392 59.588,16.352 59.628,16.255 59.628,0.509 59.588,0.412 59.491,0.372 24.714,0.372 ; 18.766,0.412 18.766,0.412 ; 18.766,0.412 18.817,0.463 18.857,0.56 ; 18.786,53.721 18.826,53.818 19.408,54.401 ; 18.786,53.721 18.786,53.721 ; 18.804,17.369 18.901,17.409 28.115,17.409 30.996,20.29 ; 18.804,17.369 18.804,17.369 ; 18.826,65.54 18.826,65.54 ; 18.826,65.54 22.106,62.26 22.203,62.22 ; 18.857,0.56 18.857,0.56 ; 18.857,0.56 18.857,2.022 19.882,2.022 19.903,2 19.903,0.509 19.943,0.412 20.041,0.372 23.393,0.372 23.491,0.412 ; 19.408,54.401 19.505,54.441 25.707,54.441 ; 19.408,54.401 19.408,54.401 ; 22.203,62.22 22.203,62.22 ; 22.203,62.22 41.275,62.22 41.372,62.26 41.412,62.357 41.412,83.461 41.372,83.558 ; 23.491,0.412 23.491,0.412 ; 23.491,0.412 23.541,0.463 23.582,0.56 ; 23.582,0.56 23.582,0.56 ; 23.582,0.56 23.582,1.95 23.603,1.971 24.454,1.971 24.526,1.899 24.526,0.559 24.566,0.462 24.568,0.461 24.617,0.412 24.714,0.372 ; 24.714,0.372 24.714,0.372 ; 25.707,54.441 25.804,54.401 26.513,53.691 26.553,53.594 ; 25.707,54.441 25.707,54.441 ; 25.898,82.274 25.898,89.303 ; 25.898,82.274 25.898,82.274 ; 25.898,82.274 25.938,82.177 26.678,81.437 26.775,81.397 ; 25.898,89.303 25.938,89.4 34.661,98.123 34.661,115.618 34.338,115.941 31.601,115.941 ; 25.898,89.303 25.898,89.303 ; 25.916,119.731 25.944,119.743 26.013,119.771 ; 25.916,119.731 25.916,119.731 ; 26.013,119.771 26.013,119.771 ; 26.013,119.771 30.353,119.771 30.45,119.731 30.49,119.634 30.49,116.665 31.448,115.707 34.185,115.707 ; 26.553,53.594 26.553,43.767 27.13,43.19 46.355,43.19 46.452,43.15 46.492,43.053 46.492,39.602 ; 26.553,53.594 26.553,53.594 ; 26.775,81.397 26.775,81.397 ; 26.775,81.397 31.899,81.397 ; 26.916,9.682 26.916,9.682 ; 26.916,9.682 27.402,10.168 27.442,10.265 ; 27.442,10.265 27.442,10.265 ; 27.442,10.265 27.442,11.859 28.908,13.325 30.883,13.325 ; 27.962,17.643 27.962,17.643 ; 27.962,17.643 28.031,17.671 28.059,17.683 ; 28.059,17.683 28.059,17.683 ; 28.059,17.683 30.94,20.564 42.948,20.564 ; 30.724,116.818 30.724,119.634 30.764,119.731 30.861,119.771 51.965,119.771 ; 30.724,116.818 30.724,116.818 ; 30.724,116.818 30.764,116.721 31.504,115.981 31.601,115.941 ; 30.883,13.325 30.883,13.325 ; 30.883,13.325 30.98,13.365 33.353,15.738 46.758,15.738 ; 30.996,20.29 31.024,20.302 31.093,20.33 ; 30.996,20.29 30.996,20.29 ; 31.093,20.33 43.101,20.33 44.821,22.05 44.821,37.487 ; 31.093,20.33 31.093,20.33 ; 31.601,115.941 31.601,115.941 ; 31.899,81.397 31.899,81.397 ; 31.899,81.397 31.968,81.425 31.996,81.437 ; 31.996,81.437 31.996,81.437 ; 31.996,81.437 32.355,81.796 32.395,81.893 ; 32.395,81.893 32.395,81.893 ; 32.395,81.893 32.395,85.646 33.099,86.35 38.91,86.35 41.646,83.614 41.646,62.357 41.686,62.26 41.783,62.22 45.641,62.22 46.726,61.135 46.726,39.449 44.861,37.584 44.821,37.487 ; 32.629,85.493 32.669,85.59 33.155,86.076 ; 32.629,85.493 32.629,85.493 ; 32.629,85.493 32.629,81.74 32.052,81.163 26.622,81.163 25.664,82.121 25.664,89.456 34.387,98.179 34.427,98.276 ; 33.155,86.076 33.252,86.116 38.757,86.116 ; 33.155,86.076 33.155,86.076 ; 34.185,115.707 34.282,115.667 34.387,115.562 ; 34.185,115.707 34.185,115.707 ; 34.387,115.562 34.427,115.465 34.427,98.276 ; 34.387,115.562 34.387,115.562 ; 34.427,98.276 34.427,98.276 ; 38.757,86.116 38.854,86.076 41.372,83.558 ; 38.757,86.116 38.757,86.116 ; 41.372,83.558 41.372,83.558 ; 42.948,20.564 42.948,20.564 ; 42.948,20.564 43.045,20.604 44.547,22.106 44.587,22.203 ; 44.587,22.203 44.587,22.203 ; 44.587,22.203 44.587,37.64 46.452,39.505 46.492,39.602 ; 44.821,37.487 44.821,37.487 ; 46.492,39.602 46.492,39.602 ; 46.758,15.738 46.758,15.738 ; 46.758,15.738 46.827,15.766 46.855,15.778 ; 46.855,15.778 46.855,15.778 ; 46.855,15.778 49.627,18.55 49.667,18.647 ; 49.667,18.647 49.667,18.647 ; 49.667,18.647 49.667,34.973 52.167,37.473 52.207,37.57 ; 50.77,73.144 50.782,73.116 50.81,73.047 ; 50.77,73.144 50.77,73.144 ; 50.77,73.144 49.54,74.374 49.54,87.805 52.421,90.686 52.461,90.783 ; 50.81,73.047 50.81,66.627 52.167,65.27 ; 50.81,73.047 50.81,73.047 ; 51.965,119.771 52.062,119.731 55.85,115.943 55.89,115.846 55.89,96.012 55.85,95.915 55.753,95.875 54.816,95.875 52.461,93.52 52.461,90.783 ; 51.965,119.771 51.965,119.771 ; 52.167,65.27 52.207,65.173 52.207,37.57 ; 52.167,65.27 52.167,65.27 ; 52.207,37.57 52.207,37.57 ; 52.461,90.783 52.461,90.783
  lines w0.508: 30.607,119.888 30.607,116.713 31.496,115.824 34.29,115.824 34.544,115.57 34.544,98.171 25.781,89.408 25.781,82.169 26.67,81.28 32.004,81.28 32.512,81.788 32.512,85.598 33.147,86.233 38.862,86.233 41.529,83.566 41.529,61.976 ; 42.672,15.621 46.863,15.621 49.784,18.542 49.784,34.925 52.324,37.465 52.324,65.278 50.927,66.675 50.927,73.152 49.657,74.422 49.657,87.757 52.578,90.678 52.578,93.472 54.864,95.758 56.007,95.758 56.007,115.951 52.07,119.888 25.908,119.888 16.637,110.617 16.637,103.886 18.669,101.854 18.669,65.532 22.098,62.103 45.593,62.103 46.609,61.087 46.609,43.561 ; 42.799,15.621 33.401,15.621 30.988,13.208 28.956,13.208 27.559,11.811 27.559,10.16 26.924,9.525 17.272,9.525 16.51,8.763 ; 14.224,8.763 16.51,8.763 ; 14.224,8.763 14.224,4.826 13.589,4.191 9.525,4.191 9.017,4.699 9.017,16.891 12.7,20.574 12.7,28.956 14.351,30.607 17.653,30.607 18.669,31.623 18.669,53.848 19.431,54.61 25.781,54.61 26.67,53.721 26.67,43.815 27.178,43.307 46.355,43.307 46.609,43.561 ; 14.224,8.763 16.51,8.763 ; 14.224,8.763 14.224,12.954 18.796,17.526 28.067,17.526 30.988,20.447 43.053,20.447 44.704,22.098 44.704,37.592 46.609,39.497 46.609,43.561
  text "3" at 17.259,60.82 h1.4
  text "B" at 17.259,58.801 h1.4
  text "L3 VCC" at 55.42,-49.21 h1.52
  text ".GP2" at 97.5,-49.2 h1.52
  text "3" at 65.1,-49.26 h1.91
L5_GND (plane layer: these items are gaps in the copper):
  region: 20.327,62.23 25.401,62.23 25.655,61.976 25.655,60.452 25.506,60.303 25.655,60.155 25.655,58.42 25.527,58.292 20.327,58.292 20.327,58.42 21.971,58.42 21.971,60.071 20.327,60.071 20.327,60.452 21.971,60.452 21.971,62.103 20.327,62.103
  region: 20.327,62.23 11.261,62.23 11.134,62.103 11.134,60.528 11.405,60.258 11.175,60.028 11.175,58.547 11.43,58.292 20.327,58.292
  pour cut-out: 52.508,116.044 52.508,97.027 33.491,97.027 33.491,116.044 52.508,116.044
  pour cut-out: 34.427,122.151 34.396,122.386 34.305,122.605 34.16,122.793 33.972,122.938 33.753,123.028 33.518,123.059 33.283,123.028 33.064,122.938 32.876,122.793 32.731,122.605 32.641,122.386 32.61,122.151 32.641,121.916 32.731,121.697 32.876,121.509 33.064,121.364 33.283,121.273 33.518,121.242 33.753,121.273 33.972,121.364 34.16,121.509 34.305,121.697 34.396,121.916 34.427,122.151
  pour cut-out: 30.027,122.151 29.996,122.386 29.905,122.605 29.76,122.793 29.572,122.938 29.353,123.028 29.118,123.059 28.883,123.028 28.664,122.938 28.476,122.793 28.331,122.605 28.241,122.386 28.21,122.151 28.241,121.916 28.331,121.697 28.476,121.509 28.664,121.364 28.883,121.273 29.118,121.242 29.353,121.273 29.572,121.364 29.76,121.509 29.905,121.697 29.996,121.916 30.027,122.151
  pour cut-out: 8.629,16.51 8.595,16.771 8.494,17.015 8.334,17.224 8.125,17.384 7.881,17.485 7.62,17.519 7.359,17.485 7.115,17.384 6.906,17.224 6.746,17.015 6.645,16.771 6.611,16.51 6.645,16.249 6.746,16.005 6.906,15.796 7.115,15.636 7.359,15.535 7.62,15.501 7.881,15.535 8.125,15.636 8.334,15.796 8.494,16.005 8.595,16.249 8.629,16.51
  pour cut-out: 8.629,21.59 8.595,21.851 8.494,22.095 8.334,22.304 8.125,22.464 7.881,22.565 7.62,22.599 7.359,22.565 7.115,22.464 6.906,22.304 6.746,22.095 6.645,21.851 6.611,21.59 6.645,21.329 6.746,21.085 6.906,20.876 7.115,20.716 7.359,20.615 7.62,20.581 7.881,20.615 8.125,20.716 8.334,20.876 8.494,21.085 8.595,21.329 8.629,21.59
  pour cut-out: 6.346,102.108 6.298,102.468 6.159,102.804 5.938,103.093 5.649,103.314 5.313,103.453 4.953,103.501 4.593,103.453 4.257,103.314 3.968,103.093 3.747,102.804 3.608,102.468 3.56,102.108 3.608,101.748 3.747,101.412 3.968,101.123 4.257,100.902 4.593,100.763 4.953,100.715 5.313,100.763 5.649,100.902 5.938,101.123 6.159,101.412 6.298,101.748 6.346,102.108
  pour cut-out: 10.015,31.242 9.989,31.434 9.915,31.614 9.797,31.768 9.643,31.886 9.463,31.96 9.271,31.986 9.079,31.96 8.899,31.886 8.745,31.768 8.627,31.614 8.553,31.434 8.527,31.242 8.553,31.05 8.627,30.87 8.745,30.716 8.899,30.598 9.079,30.524 9.271,30.498 9.463,30.524 9.643,30.598 9.797,30.716 9.915,30.87 9.989,31.05 10.015,31.242
  pour cut-out: 10.015,38.792 9.989,38.984 9.915,39.164 9.797,39.318 9.643,39.436 9.463,39.51 9.271,39.536 9.079,39.51 8.899,39.436 8.745,39.318 8.627,39.164 8.553,38.984 8.527,38.792 8.553,38.599 8.627,38.42 8.745,38.266 8.899,38.148 9.079,38.074 9.271,38.048 9.463,38.074 9.643,38.148 9.797,38.266 9.915,38.42 9.989,38.599 10.015,38.792
  pour cut-out: 13.346,102.108 13.298,102.468 13.159,102.804 12.938,103.093 12.649,103.314 12.313,103.453 11.953,103.501 11.593,103.453 11.257,103.314 10.968,103.093 10.747,102.804 10.608,102.468 10.56,102.108 10.608,101.748 10.747,101.412 10.968,101.123 11.257,100.902 11.593,100.763 11.953,100.715 12.313,100.763 12.649,100.902 12.938,101.123 13.159,101.412 13.298,101.748 13.346,102.108
  lines w0.254: 18.766,0.411 18.669,0.371 0.508,0.371 0.411,0.411 0.371,0.508 0.371,29.515 0.376,29.529 0.374,29.544 0.551,30.356 0.88,31.999 0.98,33.029 1.031,34.572 1.031,37.533 0.779,39.525 0.425,41.244 0.375,41.445 0.377,41.462 0.371,41.478 0.371,126.492 0.411,126.589 0.508,126.629 59.492,126.629 59.589,126.589 59.629,126.492 59.629,27.305 59.589,27.208 59.492,27.167 58.97,27.167 58.913,27.165 58.859,27.158 58.806,27.146 58.754,27.129 58.703,27.109 58.655,27.083 58.609,27.054 58.566,27.021 58.526,26.984 58.489,26.944 58.456,26.901 58.426,26.855 58.401,26.807 58.38,26.756 58.364,26.704 58.352,26.651 58.345,26.597 58.343,26.54 58.343,17.021 58.345,16.963 58.352,16.909 58.364,16.856 58.38,16.804 58.401,16.754 58.426,16.706 58.456,16.66 58.489,16.616 58.526,16.576 58.566,16.539 58.609,16.506 58.655,16.477 58.703,16.452 58.754,16.431 58.806,16.415 58.859,16.403 58.913,16.396 58.97,16.393 59.492,16.393 59.589,16.353 59.629,16.256 59.629,0.508 59.589,0.411 59.492,0.371 24.74,0.371 ; 18.766,0.411 18.766,0.411 ; 18.766,0.411 18.842,0.487 18.883,0.584 ; 18.883,0.584 18.883,0.584 ; 18.883,0.584 18.883,2.022 19.857,2.022 19.878,2 19.878,0.61 ; 19.878,0.61 19.878,0.61 ; 19.878,0.61 19.906,0.541 19.918,0.512 ; 19.918,0.512 19.918,0.512 ; 19.918,0.512 20.02,0.411 20.117,0.371 ; 20.117,0.371 20.117,0.371 ; 20.117,0.371 23.368,0.371 23.465,0.411 ; 23.465,0.411 23.465,0.411 ; 23.465,0.411 23.541,0.487 23.582,0.584 ; 23.582,0.584 23.582,0.584 ; 23.582,0.584 23.582,1.924 23.603,1.945 24.479,1.945 24.526,1.899 24.526,0.584 24.566,0.487 ; 24.566,0.487 24.566,0.487 ; 24.566,0.487 24.642,0.411 24.74,0.371 ; 24.74,0.371 24.74,0.371
  text "5" at 21.476,60.833 h1.4
  text "B" at 21.463,58.801 h1.4
  text "5" at 65.4,-49.21 h1.91
  text "L5 GND" at 55.62,-49.31 h1.52
  text ".GP3" at 97.59,-49.29 h1.52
